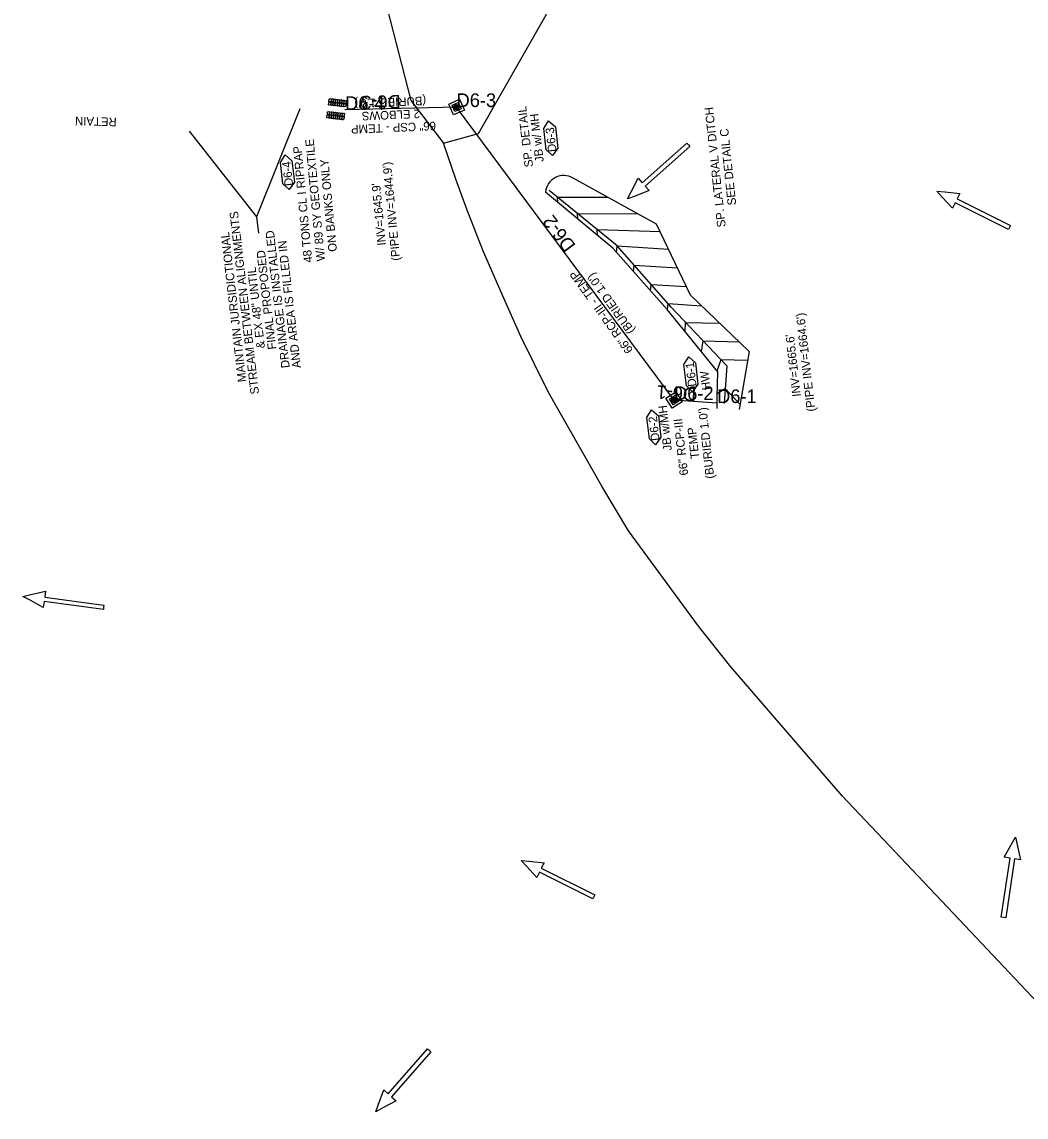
# Model space of a CAD drawing. Extents: x 465700 to 483515, y 488970 to 507540.
# Drawn here: x 474425 to 475014, y 503102 to 503745 of the extents above; entities that cross this region are included whole.
import ezdxf

# ---------------------------------------------------------------- set-up
doc = ezdxf.new("R2010")
doc.units = 0
for name, color, linetype in [('Default', 7, 'Continuous'), ('Exist Plan Preparation Drainage Flow Arrows', 7, 'Continuous'), ('Exist Plan Preparation Watershed Blue', 7, 'Continuous'), ('Prop Drainage Structure Box Number Symbol CELL', 7, 'Continuous'), ('Prop Drainage Structure Headwall CELL', 7, 'Continuous'), ('Prop Drainage Structure Headwall Label', 7, 'Continuous'), ('Prop Drainage Structure Junction Box with Manhole CELL', 7, 'Continuous'), ('Prop Drainage Structure Junction Box with Manhole Label', 7, 'Continuous'), ('Prop Drainage Structure Pipe CSP 15in Label', 7, 'Continuous'), ('Prop Drainage Structure Pipe CSP 66in', 7, 'Continuous'), ('Prop Drainage Structure Pipe CSP 66in Label', 7, 'Continuous'), ('Prop Drainage Structure Pipe RCP 60in Class III', 7, 'Continuous'), ('Prop Drainage Structure Pipe RCP 60in Class III Label', 7, 'Continuous'), ('Prop Drainage Structure Plot Symbol 20 Scale', 7, 'Continuous'), ('Prop Drainage Structure Plot Symbol 50 Scale', 7, 'Continuous'), ('Prop Drainage Structure Retain Label', 7, 'Continuous'), ('Prop Drainage Structure Tops and Inverts LABEL', 7, 'Continuous'), ('Prop Earthen Structure Head Ditch', 7, 'Continuous'), ('Prop Erosion Embankment Toe Protection Label', 7, 'Continuous'), ('Prop Erosion Rip Rap Pad at Outlet Label', 7, 'Continuous'), ('Prop Erosion Rip Rap Pad Outlet for Jurisdictional Stream CELL', 7, 'Continuous'), ('Scratch_Level_8', 7, 'Continuous')]:
    doc.layers.add(name, color=color, linetype=linetype)

# ---------------------------------------------------------------- blocks, each defined once
blk = doc.blocks.new('Existing ground flow arrow')
at = {"layer": 'Default'}
blk.add_line((2.5, -4.33), (2.5, -4.33), dxfattribs=at)
blk.add_lwpolyline([(-1.29, -47.2), (-1.28, -12.53), (-4.77, -12.53), (-1.65, -4.33), (0, 0), (1.65, -4.33), (4.78, -12.53), (1.28, -12.52), (1.29, -47.19), (0, -47.2)], close=True, dxfattribs=at)

msp = doc.modelspace()

# ---------------------------------------------------------------- linework, layer by layer
at = {"layer": 'Exist Plan Preparation Watershed Blue'}
for points in [[(475043.75, 503145.56), (474975.08, 503218.25), (474906.45, 503290.98), (474841.06, 503366.61), (474822.12, 503390.62), (474781.05, 503446.58), (474765.36, 503472.89), (474733.7, 503528.17), (474717.65, 503560.73), (474707.52, 503583.69), (474695.73, 503610.42), (474686.31, 503634.82), (474679.54, 503653.13), (474672.31, 503674.23), (474692.89, 503679.94), (474732.67, 503749.62), (474729.4, 503768.98), (474794.46, 503769.47), (474876.64, 503771.38), (474928.93, 503775.76), (475126.97, 503907.83)], [(474637.56, 503760.43), (474653.18, 503699.27), (474672.31, 503674.23), (474692.89, 503679.94), (474732.67, 503749.62)]]:
    msp.add_lwpolyline(points, dxfattribs=at)
at = {"layer": 'Prop Drainage Structure Box Number Symbol CELL'}
for points in [[(474732.71, 503670.4), (474731.27, 503682.92), (474734.01, 503687.36), (474738.02, 503683.85), (474739.46, 503671.33), (474736.36, 503666.95), (474732.71, 503670.4)], [(474578.04, 503650.41), (474576.6, 503662.93), (474579.35, 503667.38), (474583.35, 503663.86), (474584.79, 503651.34), (474581.69, 503646.96), (474578.04, 503650.41)], [(474814.99, 503531.72), (474813.55, 503544.24), (474816.3, 503548.69), (474820.3, 503545.18), (474821.74, 503532.66), (474818.64, 503528.28), (474814.99, 503531.72)], [(474793.21, 503500.6), (474791.77, 503513.12), (474794.52, 503517.56), (474798.52, 503514.05), (474799.96, 503501.53), (474796.86, 503497.15), (474793.21, 503500.6)]]:
    msp.add_lwpolyline(points, dxfattribs=at)
at = {"layer": 'Prop Drainage Structure Headwall CELL'}
for p, q in [((474833.08, 503518.34), (474832.94, 503525.04)), ((474833.01, 503521.69), (474833.01, 503521.69)), ((474833.01, 503521.69), (474833.01, 503521.69))]:
    msp.add_line(p, q, dxfattribs=at)
at = {"layer": 'Prop Drainage Structure Junction Box with Manhole CELL'}
for p, q in [((474678.76, 503694.9), (474678.76, 503694.9)), ((474679.45, 503696.73), (474679.45, 503696.73)), ((474680.02, 503695.47), (474680.02, 503695.47)), ((474680.59, 503694.21), (474680.59, 503694.21)), ((474681.29, 503696.04), (474681.29, 503696.04)), ((474806.97, 503524.56), (474806.97, 503524.56)), ((474808.89, 503524.15), (474808.89, 503524.15)), ((474806.56, 503522.65), (474806.56, 503522.65)), ((474807.72, 503523.4), (474807.72, 503523.4)), ((474808.48, 503522.24), (474808.48, 503522.24))]:
    msp.add_line(p, q, dxfattribs=at)
for points in [[(474678.65, 503695.63), (474679.04, 503695.59), (474679.04, 503695.55), (474678.64, 503695.59), (474678.64, 503695.59)], [(474679.2, 503694.36), (474679.43, 503694.68), (474679.46, 503694.66), (474679.23, 503694.33)], [(474679.47, 503696.74), (474679.64, 503696.38), (474679.6, 503696.36), (474679.44, 503696.73)], [(474680.57, 503694.2), (474680.41, 503694.56), (474680.45, 503694.58), (474680.61, 503694.21)], [(474680.82, 503696.61), (474680.58, 503696.28), (474680.62, 503696.26), (474680.85, 503696.58)], [(474681.4, 503695.35), (474681.01, 503695.39), (474681, 503695.35), (474681.4, 503695.31)], [(474806.99, 503524.57), (474807.2, 503524.24), (474807.17, 503524.22), (474806.95, 503524.55)], [(474808.34, 503524.64), (474808.16, 503524.29), (474808.19, 503524.27), (474808.37, 503524.62)], [(474806.34, 503523.35), (474806.73, 503523.37), (474806.74, 503523.33), (474806.34, 503523.31), (474806.34, 503523.31)], [(474807.07, 503522.17), (474807.25, 503522.53), (474807.29, 503522.51), (474807.11, 503522.16)], [(474808.46, 503522.22), (474808.24, 503522.56), (474808.28, 503522.58), (474808.49, 503522.25)], [(474809.11, 503523.49), (474808.71, 503523.47), (474808.71, 503523.43), (474809.11, 503523.45)]]:
    msp.add_lwpolyline(points, dxfattribs=at)
for centre, radius in [((474680.02, 503695.47), 1.39), ((474680.02, 503695.47), 0.99), ((474680.02, 503695.47), 0.953), ((474680.02, 503695.47), 0.625), ((474680.02, 503695.47), 0.333), ((474680.02, 503695.47), 0.292), ((474680.02, 503695.47), 0.0834), ((474680.02, 503695.47), 0.0417), ((474807.72, 503523.4), 1.39), ((474807.72, 503523.4), 0.99), ((474807.72, 503523.4), 0.953), ((474807.72, 503523.4), 0.625), ((474807.72, 503523.4), 0.333), ((474807.72, 503523.4), 0.292), ((474807.72, 503523.4), 0.0834), ((474807.72, 503523.4), 0.0417)]:
    msp.add_circle(centre, radius, dxfattribs=at)
at = {"layer": 'Prop Drainage Structure Pipe CSP 66in'}
msp.add_line((474680.02, 503695.47), (474614.48, 503693.83), dxfattribs=at)
at = {"layer": 'Prop Drainage Structure Pipe RCP 60in Class III'}
for p, q in [((474807.72, 503523.4), (474680.02, 503695.47)), ((474833.01, 503521.62), (474807.72, 503523.4))]:
    msp.add_line(p, q, dxfattribs=at)
at = {"layer": 'Prop Drainage Structure Plot Symbol 20 Scale'}
for points in [[(474681.03, 503698.11), (474682.67, 503694.47), (474679.02, 503692.83), (474677.38, 503696.47)], [(474808.32, 503526.16), (474810.49, 503522.81), (474807.13, 503520.63), (474804.96, 503523.99)]]:
    msp.add_lwpolyline(points, close=True, dxfattribs=at)
for centre in [(474680.02, 503695.47), (474807.72, 503523.4)]:
    msp.add_circle(centre, 1.5, dxfattribs=at)
at = {"layer": 'Prop Drainage Structure Plot Symbol 50 Scale'}
for points in [[(474681.78, 503700.1), (474684.65, 503693.71), (474678.26, 503690.84), (474675.4, 503697.23)], [(474808.76, 503528.24), (474812.56, 503522.36), (474806.69, 503518.56), (474802.88, 503524.43)]]:
    msp.add_lwpolyline(points, close=True, dxfattribs=at)
for centre in [(474680.02, 503695.47), (474807.72, 503523.4)]:
    msp.add_circle(centre, 1.5, dxfattribs=at)
at = {"layer": 'Prop Earthen Structure Head Ditch'}
msp.add_line((474838.75, 503543.48), (474837.13, 503521.35), dxfattribs=at)
for points in [[(474851.74, 503551.89), (474817.43, 503584.88), (474797.44, 503626.76), (474748.47, 503653.69)], [(474838.75, 503543.48), (474805.96, 503578), (474774.27, 503613.95), (474734.39, 503646.52)], [(474838.75, 503543.48), (474805.96, 503578), (474774.27, 503613.95), (474734.39, 503646.52)], [(474832.94, 503525.04), (474833.4, 503540.02), (474803.65, 503576.62), (474771.77, 503612.56), (474732.22, 503645.42)], [(474739.53, 503639.35), (474739.29, 503642.52), (474768.64, 503642.6)], [(474751.22, 503629.64), (474750.96, 503632.99), (474786.69, 503632.67)], [(474762.85, 503619.97), (474762.64, 503623.45), (474799.57, 503622.29)], [(474773.98, 503610.07), (474774.31, 503613.91), (474804.48, 503612.01)], [(474783.96, 503598.82), (474784.28, 503602.6), (474809.74, 503601)], [(474793.9, 503587.61), (474794.25, 503591.29), (474814.99, 503589.99)], [(474803.85, 503576.37), (474804.22, 503579.99), (474823.8, 503578.75)], [(474814.3, 503563.51), (474814.53, 503568.99), (474834.49, 503568.47)], [(474823.91, 503551.7), (474824.91, 503558.06), (474845.89, 503557.52)], [(474851.74, 503551.89), (474846.03, 503517.76)], [(474832.99, 503540.53), (474835.29, 503547.13), (474850.66, 503546.73)], [(474833.02, 503527.21), (474837.72, 503530.25), (474846.53, 503520.73)]]:
    msp.add_lwpolyline(points, dxfattribs=at)
msp.add_arc((474742.95, 503644.44), 10.78, 59.15426, 174.78516, dxfattribs=at)
at = {"layer": 'Prop Erosion Embankment Toe Protection Label'}
for points in [[(474587.95, 503694.43), (474562.61, 503631.04), (474563.69, 503621.47)], [(474522.92, 503681.32), (474562.61, 503631.04), (474562.61, 503631.04)]]:
    msp.add_lwpolyline(points, dxfattribs=at)
at = {"layer": 'Prop Erosion Rip Rap Pad Outlet for Jurisdictional Stream CELL'}
msp.add_line((474614.61, 503693.76), (474614.61, 503693.76), dxfattribs=at)
msp.add_line((474614.61, 503693.76), (474614.61, 503693.76), dxfattribs=at)
for points in [[(474606.2, 503698.46), (474606.2, 503697.86), (474606.08, 503696.79), (474605.29, 503696.53), (474604.81, 503696.76), (474605.06, 503698.17), (474605.62, 503698.53), (474606.2, 503698.46)], [(474606.42, 503700.35), (474606.43, 503699.74), (474606.3, 503698.68), (474605.52, 503698.42), (474605.04, 503698.65), (474605.28, 503700.06), (474605.84, 503700.42), (474606.42, 503700.35)], [(474607.44, 503698.31), (474607.46, 503697.71), (474607.33, 503696.64), (474606.53, 503696.38), (474606.06, 503696.62), (474606.31, 503698.02), (474606.87, 503698.38), (474607.44, 503698.31)], [(474607.67, 503700.2), (474607.68, 503699.59), (474607.56, 503698.53), (474606.76, 503698.27), (474606.28, 503698.5), (474606.54, 503699.91), (474607.1, 503700.27), (474607.67, 503700.2)], [(474608.7, 503698.17), (474608.71, 503697.56), (474608.58, 503696.49), (474607.79, 503696.23), (474607.31, 503696.47), (474607.57, 503697.87), (474608.11, 503698.23), (474608.7, 503698.17)], [(474608.92, 503700.05), (474608.94, 503699.45), (474608.81, 503698.38), (474608.01, 503698.12), (474607.53, 503698.35), (474607.79, 503699.76), (474608.34, 503700.12), (474608.92, 503700.05)], [(474609.95, 503698.02), (474609.95, 503697.41), (474609.83, 503696.34), (474609.04, 503696.08), (474608.56, 503696.32), (474608.81, 503697.72), (474609.35, 503698.09), (474609.95, 503698.02)], [(474610.17, 503699.9), (474610.18, 503699.3), (474610.05, 503698.23), (474609.26, 503697.97), (474608.79, 503698.2), (474609.03, 503699.61), (474609.58, 503699.97), (474610.17, 503699.9)], [(474611.19, 503697.87), (474611.19, 503697.26), (474611.07, 503696.2), (474610.28, 503695.94), (474609.8, 503696.17), (474610.05, 503697.58), (474610.61, 503697.94), (474611.19, 503697.87)], [(474611.41, 503699.75), (474611.42, 503699.15), (474611.29, 503698.08), (474610.51, 503697.82), (474610.03, 503698.06), (474610.27, 503699.46), (474610.83, 503699.82), (474611.41, 503699.75)], [(474612.43, 503697.72), (474612.45, 503697.11), (474612.32, 503696.05), (474611.52, 503695.79), (474611.05, 503696.02), (474611.3, 503697.43), (474611.86, 503697.79), (474612.43, 503697.72)], [(474612.66, 503699.61), (474612.67, 503699), (474612.54, 503697.93), (474611.75, 503697.68), (474611.27, 503697.91), (474611.53, 503699.31), (474612.08, 503699.68), (474612.66, 503699.61)], [(474613.68, 503697.57), (474613.7, 503696.96), (474613.57, 503695.9), (474612.78, 503695.64), (474612.3, 503695.87), (474612.55, 503697.28), (474613.1, 503697.64), (474613.68, 503697.57)], [(474613.91, 503699.46), (474613.93, 503698.85), (474613.8, 503697.78), (474613, 503697.53), (474612.52, 503697.76), (474612.78, 503699.16), (474613.33, 503699.53), (474613.91, 503699.46)], [(474615.16, 503699.31), (474615.17, 503698.7), (474615.04, 503697.64), (474614.25, 503697.38), (474613.78, 503697.61), (474614.02, 503699.02), (474614.57, 503699.38), (474615.16, 503699.31)], [(474604.15, 503690.95), (474604.14, 503691.56), (474604.27, 503692.62), (474605.06, 503692.88), (474605.53, 503692.65), (474605.29, 503691.24), (474604.74, 503690.88), (474604.15, 503690.95)], [(474605.4, 503690.8), (474605.39, 503691.41), (474605.51, 503692.48), (474606.31, 503692.73), (474606.79, 503692.5), (474606.53, 503691.1), (474605.99, 503690.73), (474605.4, 503690.8)], [(474606.66, 503690.65), (474606.64, 503691.26), (474606.77, 503692.33), (474607.57, 503692.58), (474608.04, 503692.35), (474607.79, 503690.95), (474607.23, 503690.59), (474606.66, 503690.65)], [(474607.9, 503690.51), (474607.89, 503691.11), (474608.02, 503692.18), (474608.81, 503692.44), (474609.28, 503692.2), (474609.04, 503690.8), (474608.48, 503690.44), (474607.9, 503690.51)], [(474609.14, 503690.36), (474609.13, 503690.96), (474609.26, 503692.03), (474610.05, 503692.29), (474610.52, 503692.06), (474610.28, 503690.65), (474609.73, 503690.29), (474609.14, 503690.36)], [(474610.39, 503690.21), (474610.38, 503690.81), (474610.5, 503691.88), (474611.3, 503692.14), (474611.78, 503691.91), (474611.52, 503690.5), (474610.97, 503690.14), (474610.39, 503690.21)], [(474611.65, 503690.06), (474611.63, 503690.67), (474611.76, 503691.73), (474612.55, 503691.99), (474613.03, 503691.76), (474612.78, 503690.35), (474612.22, 503689.99), (474611.65, 503690.06)], [(474612.89, 503689.91), (474612.88, 503690.52), (474613.01, 503691.58), (474613.8, 503691.84), (474614.27, 503691.61), (474614.03, 503690.2), (474613.47, 503689.84), (474612.89, 503689.91)], [(474614.94, 503697.42), (474614.94, 503696.82), (474614.82, 503695.75), (474614.03, 503695.49), (474613.55, 503695.72), (474613.8, 503697.13), (474614.34, 503697.49), (474614.94, 503697.42)], [(474603.92, 503689.07), (474603.92, 503689.67), (474604.05, 503690.74), (474604.83, 503691), (474605.31, 503690.76), (474605.07, 503689.36), (474604.52, 503688.99), (474603.92, 503689.07)], [(474605.18, 503688.92), (474605.16, 503689.52), (474605.29, 503690.59), (474606.09, 503690.85), (474606.56, 503690.61), (474606.31, 503689.21), (474605.76, 503688.85), (474605.18, 503688.92)], [(474606.43, 503688.77), (474606.41, 503689.37), (474606.54, 503690.44), (474607.34, 503690.7), (474607.82, 503690.47), (474607.56, 503689.06), (474607, 503688.7), (474606.43, 503688.77)], [(474607.67, 503688.62), (474607.67, 503689.22), (474607.8, 503690.29), (474608.58, 503690.55), (474609.06, 503690.32), (474608.81, 503688.91), (474608.26, 503688.55), (474607.67, 503688.62)], [(474608.91, 503688.47), (474608.91, 503689.08), (474609.04, 503690.14), (474609.82, 503690.4), (474610.3, 503690.17), (474610.06, 503688.76), (474609.51, 503688.4), (474608.91, 503688.47)], [(474610.17, 503688.32), (474610.15, 503688.93), (474610.28, 503690), (474611.08, 503690.25), (474611.55, 503690.02), (474611.3, 503688.62), (474610.75, 503688.25), (474610.17, 503688.32)], [(474611.42, 503688.17), (474611.4, 503688.78), (474611.53, 503689.85), (474612.33, 503690.1), (474612.81, 503689.87), (474612.55, 503688.47), (474611.99, 503688.1), (474611.42, 503688.17)], [(474612.66, 503688.03), (474612.66, 503688.63), (474612.79, 503689.7), (474613.57, 503689.96), (474614.05, 503689.72), (474613.8, 503688.32), (474613.25, 503687.96), (474612.66, 503688.03)]]:
    msp.add_lwpolyline(points, dxfattribs=at)
at = {"layer": 'Scratch_Level_8'}
for p, q in [((474680.02, 503695.47), (474614.61, 503693.76)), ((474807.72, 503523.4), (474680.02, 503695.47)), ((474833.01, 503521.62), (474807.72, 503523.4))]:
    msp.add_line(p, q, dxfattribs=at)

# ---------------------------------------------------------------- block references
at = {"layer": 'Exist Plan Preparation Drainage Flow Arrows'}
for p, xscale, yscale, rotation in [((474780.45, 503641.55), 1.0124070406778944, 1.012407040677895, 131.6583140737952), ((474962.03, 503646.07), 1.0124070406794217, 1.0124070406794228, 63.39053053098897), ((474425.41, 503408.03), 1.0124070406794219, 1.0124070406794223, 82.33441044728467), ((475008.19, 503266.69), 1.0124070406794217, 1.0124070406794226, -8.455627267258), ((474717.85, 503253.01), 1.012407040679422, 1.0124070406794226, 63.476107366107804), ((474632.54, 503105.42), 1.0124070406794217, 1.0124070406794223, 139.01156519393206)]:
    msp.add_blockref('Existing ground flow arrow', p, dxfattribs=dict(at, xscale=xscale, yscale=yscale, rotation=rotation))

# ---------------------------------------------------------------- texts
at = {"layer": 'Prop Drainage Structure Box Number Symbol CELL'}
for s, p in [('D6-3', (474738.76, 503669.33)), ('D6-4', (474584.09, 503649.37)), ('D6-1', (474820.94, 503531.53)), ('D6-2', (474799.25, 503499.69))]:
    msp.add_text(s, height=5, rotation=96.55096, dxfattribs=at).set_placement(p)
at = {"layer": 'Prop Drainage Structure Headwall Label'}
msp.add_text('HW', height=5, rotation=96.55384, dxfattribs=at).set_placement((474829.17, 503529.54))
at = {"layer": 'Prop Drainage Structure Junction Box with Manhole Label'}
for s, p in [('SP. DETAIL ', (474724.97, 503660.41)), ('JB w/ MH', (474731.21, 503663.47)), ('JB w/MH', (474806.44, 503493.98))]:
    msp.add_text(s, height=5, rotation=96.55384, dxfattribs=at).set_placement(p)
at = {"layer": 'Prop Drainage Structure Pipe CSP 15in Label'}
for s, p in [('SP. LATERAL V DITCH', (474838.06, 503625.1)), ('SEE DETAIL C', (474844.24, 503638.02))]:
    msp.add_text(s, height=5, rotation=96.00896, dxfattribs=at).set_placement(p)
at = {"layer": 'Prop Drainage Structure Pipe CSP 66in Label'}
for s, p in [("(BURIED 1.0')", (474662.03, 503701.67)), ('2 ELBOWS', (474658.39, 503694.01)), ('66" CSP - TEMP', (474667.8, 503686.9))]:
    msp.add_text(s, height=5, rotation=182.40683, dxfattribs=at).set_placement(p)
at = {"layer": 'Prop Drainage Structure Pipe RCP 60in Class III Label'}
for s, rotation, p in [('66" RCP-III - TEMP', 125.58623, (474783.91, 503552.83)), ("(BURIED 1.0')", 125.58623, (474784.89, 503564.35)), ("(BURIED 1.0')", 96.23512, (474831.34, 503477.45)), ('66" RCP-III', 96.23512, (474816.04, 503479.37)), ('TEMP', 96.23512, (474822.52, 503489.17))]:
    msp.add_text(s, height=5, rotation=rotation, dxfattribs=at).set_placement(p)
at = {"layer": 'Prop Drainage Structure Retain Label'}
msp.add_text('RETAIN', height=5, rotation=178.42722, dxfattribs=at).set_placement((474480.52, 503689.15))
at = {"layer": 'Prop Drainage Structure Tops and Inverts LABEL'}
for s, rotation, p in [("(PIPE INV=1644.9')", 95.33762, (474646.89, 503605.42)), ("INV=1645.9'", 95.33762, (474638.52, 503614.36)), ("(PIPE INV=1664.6')", 96.42404, (474890.69, 503516.87)), ("INV=1665.6'", 96.42404, (474882.16, 503525.64))]:
    msp.add_text(s, height=5, rotation=rotation, dxfattribs=at).set_placement(p)
at = {"layer": 'Prop Erosion Embankment Toe Protection Label'}
for s, p in [('STREAM BETWEEN ALIGNMENTS ', (474564.04, 503527.06)), ('MAINTAIN JURSIDICTIONAL ', (474556.61, 503534.2)), ('DRAINAGE IS INSTALLED', (474582.06, 503542.43)), ('AND AREA IS FILLED IN', (474588.66, 503542.4)), ('FINAL PROPOSED', (474574.19, 503553.34)), ('& EX 48" UNTIL', (474567.52, 503553.99))]:
    msp.add_text(s, height=5, rotation=96.60736, dxfattribs=at).set_placement(p)
at = {"layer": 'Prop Erosion Rip Rap Pad at Outlet Label'}
for s, p in [('48 TONS CL I RIPRAP', (474595.34, 503604.28)), ('W/ 89 SY GEOTEXTILE', (474602.79, 503605.12)), ('ON BANKS ONLY', (474609.8, 503610.7))]:
    msp.add_text(s, height=5, rotation=95.33762, dxfattribs=at).set_placement(p)
at = {"layer": 'Scratch_Level_8'}
for s, p in [('D6-4', (474614.61, 503693.76)), ('D6-3', (474680.02, 503695.47)), ('D6-2', (474807.72, 503523.4)), ('D6-1', (474833.01, 503521.62))]:
    msp.add_text(s, height=8, dxfattribs=at).set_placement(p)
for s, rotation, p in [('D6-3', 181.4973, (474647.11, 503702.61)), ('D6-2', 126.58048, (474750.3, 503614.2)), ('D6-1', 175.97441, (474820.93, 503530.49))]:
    msp.add_text(s, height=8, rotation=rotation, dxfattribs=at).set_placement(p)

doc.saveas('drawing.dxf')
